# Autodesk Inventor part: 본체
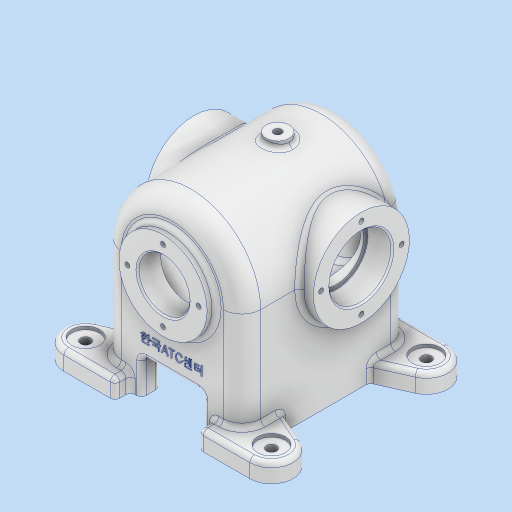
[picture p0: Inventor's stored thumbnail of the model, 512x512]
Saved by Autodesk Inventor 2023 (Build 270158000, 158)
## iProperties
Created: 2024-09
Part Number: 본체
Material: 알루미늄 6061
Document SubType Name: Modeling
Designer: asung
Density: 2.7 g/cm^3
Appearance: 알루미늄 - 평지
Mass: 1413.69 g
Surface Area: 1146.32 cm^2
Volume: 523.59 cm^3
Author: asung
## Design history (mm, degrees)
sketch "스케치1"
  geometry: L1 (-45, 0)-(45, 0); L2 (45, 0)-(45, -76); L3 (45, -76)-(-45, -76); L4 (-45, -76)-(-45, 0); L5 (-45, 0)-(45, -76); L6 (45, 0)-(-45, -76); L7 (-20, -53)-(20, -53); L8 (20, -53)-(20, -76); L9 (20, -76)-(-20, -76); L10 (-20, -76)-(-20, -53); L11 (-20, -53)-(20, -76); L12 (20, -53)-(-20, -76); C1 r 45 at (0, 0); 9 further points
  constraints: 24 end point, 7 midpoint, 4 parallel, 2 coincident, 2 horizontal, 2 perpendicular, 1 centre point
  dimensions: "d0" = 90 diameter of C1; "d2" = 90 distance of L2.end L3.end; "d3" = 76 distance of L1.end L2.end; "d4" = 40 distance of L8.end L9.end; "d5" = 23 distance of L7.end L8.end
extrude "돌출1" new body sketch "스케치1" stored distance "d6" = 108; taper "d7" = 0 deg
sketch "스케치2"
  geometry: C1 r 28.5 at (0, 0); 1 further point
  constraints: 1 centre point, 1 coincident
  dimensions: "d8" = 57 diameter of C1
extrude "돌출2" join sketch "스케치2" distance "d9" = 6; taper "d10" = 0 deg
node "작업 평면2"
sketch "스케치3"
  geometry: L1 (28.5, 60)-(-28.5, 60) reference; C1 r 31 at (0, -14); 2 further points
  constraints: 1 centre point, 1 midpoint, 1 vertical alignment
  dimensions: "d80" = 62 diameter of C1; "d81" = 74 distance from line of L1 C1.centre
extrude "돌출3" join sketch "스케치3" stored distance "d13" = 6; taper "d14" = 0 deg
sketch "스케치6"
  geometry: L1 (-28.5, 54)-(-28.5, 60) reference; L2 (-28.5, 60)-(28.5, 60) reference; L3 (28.5, 60)-(28.5, 54) reference; L4 (28.5, 54)-(45, 54) reference; L5 (45, 54)-(45, -54) reference; L6 (45, -54)-(-53, -54) reference; L7 (-53, -54)-(-53, 54) reference; L8 (-53, 54)-(-28.5, 54) reference; L9 (0, -54)-(0, 54) reference; L10 (0, -54)-(0, 60); L11 (28.5, 60)-(-28.5, 60) reference; L12 (0, -45)-(33, -45); L13 (36, -42)-(36, 42); L14 (33, 45)-(0, 45); L15 (0, 45)-(0, -45); A1 r 3 centre (33, -42) between (33, -45) and (36, -42); A2 r 3 centre (33, 42) between (36, 42) and (33, 45); 5 further points
  constraints: 10 end point, 4 point on circle, 4 tangent, 2 centre point, 2 parallel, 1 equal radius, 1 horizontal, 1 midpoint, 1 perpendicular, 1 point on line
  dimensions: "d29" = 9 distance between parallel lines of L13 L5; "d30" = 9 distance between parallel lines of L12 L6; "d31" = 9 distance between parallel lines of L4 L14; "d32" = 3 radius of A1
revolve "회전1" sketch "스케치6" stored, may be unused: angle "d33" = 90 deg
sketch "스케치7"
  geometry: C1 r 28.5 at (0, 0) reference; 2 further points
  constraints: 1 coincident
hole "구멍3" sketch "스케치7" at (0, 0) diameter "d34" = 33; stored, may be unused: countersink angle "d38" = 90 deg, drill point angle "d40" = 118 deg; dims "d35" = 6, "d36" = 40, "d37" = 16, "d39" = 60
chamfer "모따기1" distance "d41" = 1; stored, may be unused: second distance "d42" = 2, angle "d43" = 45 deg
fillet "모깎기1" dims "d44" = 12
node "작업 평면3"
sketch "스케치11" dims "d69" = 46
  geometry: C1 r 16.5 at (0, 0) reference; 3 further points
  constraints: 2 vertical alignment, 1 coincident, 2 other
hole "구멍6" sketch "스케치11" at (0, 23) diameter "d70" = 3.242; stored, may be unused: countersink angle "d74" = 90 deg, drill point angle "d76" = 118 deg; dims "d71" = 8, "d72" = 4, "d73" = 2, "d75" = 10
sketch "스케치12"
  geometry: C1 r 31 at (0, 0) reference; 2 further points
  constraints: 1 coincident
hole "구멍7" sketch "스케치12" at (0, 0) diameter "d82" = 35; stored, may be unused: countersink angle "d86" = 90 deg, drill point angle "d88" = 118 deg; dims "d83" = 8, "d84" = 40, "d85" = 16, "d87" = 100
sketch "스케치13"
  geometry: C1 r 31 at (0, 0) reference; 2 further points
  constraints: 1 coincident
hole "구멍8" sketch "스케치13" at (0, 0) diameter "d89" = 35; stored, may be unused: countersink angle "d93" = 90 deg, drill point angle "d95" = 118 deg; dims "d90" = 6, "d91" = 40, "d92" = 16, "d94" = 100
chamfer "모따기2" distance "d96" = 1; stored, may be unused: second distance "d97" = 2, angle "d98" = 45 deg
fillet "모깎기4" dims "d99" = 0.3
fillet "모깎기5" dims "d100" = 3
node "작업 평면5"
sketch "스케치14"
  geometry: L1 (48.5, 114)-(-8.5, 114) reference; L2 (74, 9)-(74, 71) reference; C1 r 7.5 at (20, 40); 2 further points
  constraints: 1 centre point, 1 midpoint, 1 vertical alignment
  dimensions: "d102" = 15 diameter of C1; "d103" = 74 distance from line of L1 C1.centre
extrude "돌출5" join sketch "스케치14" stored distance "d104" = 10; taper "d105" = 0 deg
fillet "모깎기6" dims "d110" = 3
sketch "스케치16"
  geometry: C1 r 7.5 at (0, 0) reference; 2 further points
  constraints: 1 coincident
hole "구멍9" sketch "스케치16" at (0, 0) diameter "d111" = 5.1881; stored, may be unused: countersink angle "d115" = 90 deg, drill point angle "d117" = 118 deg; dims "d112" = 20, "d113" = 40, "d114" = 16, "d116" = 21
sketch "스케치18" dims "d125" = 52
  geometry: C1 r 31 at (0, 0) reference; C2 r 21 at (0, 0) reference; 3 further points
  constraints: 2 vertical alignment, 1 coincident, 2 other
hole "구멍11" sketch "스케치18" at (0, 26) diameter "d126" = 3.242; stored, may be unused: countersink angle "d130" = 90 deg, drill point angle "d132" = 118 deg; dims "d127" = 8, "d128" = 4, "d129" = 2, "d131" = 10
sketch "스케치19"
  geometry: L1 (0, 0)-(-13, 0) reference; L2 (0, 0)-(0, 108) reference; L3 (-13, 108)-(0, 108) reference; L4 (-25, 96)-(-25, 12) reference; L5 (65, 12)-(65, 96) reference; L6 (40, 108)-(53, 108) reference; L7 (40, 0)-(40, 108) reference; L8 (53, 0)-(40, 0) reference; L9 (-40, -10)-(-7, -10); L10 (-7, -10)-(-7, 0); L11 (-25, 26)-(-45.693, 16.79); L12 (-25, 54)-(65, 54); L13 (18.379, 114)-(21.621, 114) reference; L14 (40, 0)-(0, 0) reference; L15 (20, 0)-(20, 108); L16 (0, 108)-(40, 108) reference; L17 (20, 114)-(20, 108); L18 (21.621, 104)-(21.621, 114) reference; L19 (-7, 118)-(-7, 108); L20 (-40, 118)-(-7, 118); L21 (-25, 82)-(-45.693, 91.21); L22 (47, -10)-(47, 0); L23 (80, -10)-(47, -10); L24 (65, 26)-(85.693, 16.79); L25 (65, 82)-(85.693, 91.21); L26 (80, 118)-(47, 118); L27 (47, 118)-(47, 108); A1 r 12 centre (-13, 12) between (-25, 12) and (-13, 0) reference; A2 r 12 centre (-13, 96) between (-13, 108) and (-25, 96) reference; A3 r 12 centre (53, 12) between (53, 0) and (65, 12) reference; A4 r 12 centre (53, 96) between (65, 96) and (53, 108) reference; A5 r 14 centre (-40, 4) between (-40, -10) and (-45.693, 16.79); A6 r 14 centre (-40, 104) between (-40, 118) and (-45.693, 91.21); A7 r 14 centre (80, 4) between (80, -10) and (85.693, 16.79); A8 r 14 centre (80, 104) between (80, 118) and (85.693, 91.21); 7 further points
  constraints: 30 end point, 18 symmetric about line, 8 point on circle, 5 midpoint, 4 centre point, 2 point on line, 2 tangent, 1 horizontal, 1 parallel, 1 perpendicular, 3 other
  dimensions: "d136" = 28 diameter of A5; "d137" = 60 horizontal distance of point (20, 54) A5.centre; "d138" = 18 distance between parallel lines of L10 L4; "d139" = 36 vertical distance of L9.start L11.start; "d140" = 50 vertical distance of L12.start A5.centre; "d199" = 36 vertical distance of L20.start L21.start (derived); "d200" = 36 vertical distance of L24.start L23.start (derived); "d201" = 36 vertical distance of L26.start L25.start (derived)
extrude "돌출7" join sketch "스케치19" distance "d141" = 12; taper "d142" = 0 deg
fillet "모깎기7" dims "d143" = 3
sketch "스케치21"
  geometry: L1 (-7, -7)-(-7, -3) reference; L2 (0, 0)-(-4, 0) reference; L3 (0, 0)-(0, 108) reference; L4 (-4, 108)-(0, 108) reference; L5 (-7, 111)-(-7, 115) reference; L6 (-10, 118)-(-40, 118) reference; L7 (-45.693, 91.21)-(-25, 82) reference; L8 (-25, 82)-(-25, 27.949) reference; L9 (-26.78, 25.208)-(-45.693, 16.79) reference; L10 (-40, -10)-(-10, -10) reference; L11 (56, 96)-(56, 12) reference; L12 (50, -10)-(80, -10) reference; L13 (85.693, 16.79)-(66.78, 25.208) reference; L14 (65, 27.949)-(65, 80.051) reference; L15 (66.78, 82.792)-(85.693, 91.21) reference; L16 (80, 118)-(50, 118) reference; L17 (47, 115)-(47, 111) reference; L18 (40, 108)-(44, 108) reference; L19 (40, 0)-(40, 108) reference; L20 (44, 0)-(40, 0) reference; L21 (47, -3)-(47, -7) reference; L22 (53, 9)-(-13, 9); L23 (-16, 12)-(-16, 96); L24 (-13, 99)-(53, 99); L25 (56, 96)-(56, 12); L26 (56, 9)-(-16, 99); L27 (-16, 9)-(56, 99); A1 r 3 centre (-10, -7) between (-10, -10) and (-7, -7) reference; A2 r 3 centre (-4, -3) between (-4, 0) and (-7, -3) reference; A3 r 3 centre (-4, 111) between (-7, 111) and (-4, 108) reference; A4 r 3 centre (-10, 115) between (-7, 115) and (-10, 118) reference; A5 r 14 centre (-40, 104) between (-40, 118) and (-45.693, 91.21) reference; A6 r 3 centre (-28, 27.949) between (-26.78, 25.208) and (-25, 27.949) reference; A7 r 14 centre (-40, 4) between (-45.693, 16.79) and (-40, -10) reference; A8 r 3 centre (50, -7) between (47, -7) and (50, -10) reference; A9 r 14 centre (80, 4) between (80, -10) and (85.693, 16.79) reference; A10 r 3 centre (68, 27.949) between (65, 27.949) and (66.78, 25.208) reference; A11 r 3 centre (68, 80.051) between (66.78, 82.792) and (65, 80.051) reference; A12 r 14 centre (80, 104) between (85.693, 91.21) and (80, 118) reference; A13 r 3 centre (50, 115) between (50, 118) and (47, 115) reference; A14 r 3 centre (44, 111) between (44, 108) and (47, 111) reference; A15 r 3 centre (44, -3) between (47, -3) and (44, 0) reference; A16 r 3 centre (-13, 12) between (-16, 12) and (-13, 9); A17 r 3 centre (-13, 96) between (-13, 99) and (-16, 96); A18 r 3 centre (53, 12) between (53, 9) and (56, 12); A19 r 3 centre (53, 96) between (56, 96) and (53, 99); 4 further points
  constraints: 12 end point, 8 point on circle, 8 point on line, 8 tangent, 4 centre point, 3 equal radius, 2 midpoint, 2 parallel, 1 horizontal, 1 perpendicular
  dimensions: "d149" = 9 distance between parallel lines of L8 L23; "d150" = 9 distance between parallel lines of L14 L25; "d151" = 9 distance between parallel lines of L4 L24; "d152" = 9 distance between parallel lines of L22 L2; "d153" = 3 radius of A16 (derived)
  node "투영된 루프4"
  node "투영된 루프5"
sketch "스케치22"
  geometry: L1 (38.3, -14.283)-(53, -14.283) reference; L2 (54, -15.652)-(54, -27.659) reference; L3 (54, -27.659)-(48, -27.659) reference; L4 (45, -30.984)-(45, -76) reference; L5 (45, -76)-(20, -76) reference; L6 (-20, -76)-(-45, -76) reference; L7 (-45, -76)-(-45, -30.984) reference; L8 (-48, -27.659)-(-54, -27.659) reference; L9 (-54, -27.659)-(-54, -15.652) reference; L10 (-53, -14.283)-(-38.3, -14.283) reference; L11 (-38, -13.86)-(-38, -10.5) reference; L12 (-38, -10.5)-(-34.435, -10.5) reference; L13 (34.435, -10.5)-(38, -10.5) reference; L14 (38, -10.5)-(38, -13.86) reference; L15 (38, 13.86)-(38, 10.5) reference; L16 (38, 10.5)-(34.435, 10.5) reference; L17 (-34.435, 10.5)-(-38, 10.5) reference; L18 (-38, 10.5)-(-38, 13.86) reference; L19 (-38.3, 14.283)-(-53, 14.283) reference; L20 (-54, 15.652)-(-54, 27.659) reference; L21 (-54, 27.659)-(-37.199, 27.659) reference; L22 (37.199, 27.659)-(54, 27.659) reference; L23 (54, 27.659)-(54, 15.652) reference; L24 (53, 14.283)-(38.3, 14.283) reference; L25 (-36, -45)-(-36, -27); L26 (20, -76)-(20, -53) reference; L27 (20, -53)-(-20, -53) reference; L28 (-20, -53)-(-20, -76) reference; L29 (-36, -45)-(-36, -76); L30 (-60, -76)-(-30, -76) reference; L31 (30, -76)-(60, -76) reference; L32 (36, -76)-(36, -27); L33 (36, -76)-(89.801, -76); A1 r 36 centre (0, 0) between (-34.435, -10.5) and (34.435, -10.5) reference; A2 r 36 centre (0, 0) between (34.435, 10.5) and (-34.435, 10.5) reference; A3 r 45 centre (0, 0) between (34.369, 29.047) and (-34.369, 29.047) reference; A4 r 45 centre (0, 0) between (-36, -27) and (36, -27); 5 further points
  constraints: 8 end point, 2 point on circle, 2 point on line, 1 centre point, 1 coincident, 1 horizontal, 1 perpendicular, 1 vertical, 12 other
  dimensions: "d156" = 90 diameter of A4; "d162" = 9 distance between parallel lines of L4 L32
extrude "돌출11" cut sketch "스케치22" stored distance "d163" = 84; taper "d164" = 0 deg
node "작업 평면6"
node "작업 평면7"
node "작업 평면8"
sketch "스케치24"
  geometry: L1 (28.5, 60)-(-28.5, 60) reference; C1 r 7.5 at (0, -14); 2 further points
  constraints: 1 centre point, 1 midpoint, 1 vertical alignment
  dimensions: "d169" = 15 diameter of C1; "d170" = 74 distance from line of L1 C1.centre
extrude "돌출12" join sketch "스케치24" stored distance "d171" = 10; taper "d172" = 0 deg
fillet "모깎기9" dims "d173" = 3
sketch "스케치25"
  geometry: C1 r 7.5 at (0, 0) reference; 2 further points
  constraints: 1 coincident
hole "구멍12" sketch "스케치25" at (0, 0) diameter "d174" = 5.1881; stored, may be unused: countersink angle "d178" = 90 deg, drill point angle "d180" = 118 deg; dims "d175" = 20, "d176" = 4, "d177" = 2, "d179" = 21
fillet "모깎기10" dims "d181" = 3
fillet "모깎기11" dims "d182" = 3
fillet "모깎기14" dims "d185" = 3
fillet "모깎기15" dims "d186" = 3
fillet "모깎기16" dims "d187" = 3
sketch "스케치26"
  geometry: A1 r 11 centre (80, -104) between (80, -115) and (84.473, -93.95) reference; A2 r 11 centre (80, -4) between (84.473, -14.05) and (80, 7) reference; A3 r 11 centre (-40, -104) between (-44.473, -93.95) and (-40, -115) reference; A4 r 14 centre (-40, -4) between (-40, 10) and (-45.693, -16.79) reference; 5 further points
  constraints: 4 coincident
hole "구멍13" sketch "스케치26" at (80, -104), (80, -4), (-40, -104), (-40, -4) diameter "d188" = 6.6; stored, may be unused: countersink angle "d192" = 90 deg, drill point angle "d194" = 118 deg; dims "d189" = 20, "d190" = 18, "d191" = 2, "d193" = 21
fillet "모깎기17" dims "d195" = 3
sketch "스케치27"
  geometry: L1 (60, -76)-(74, -76) reference; L2 (-17, -53)-(17, -53) reference; 4 further points
  constraints: 1 midpoint, 1 vertical alignment, 1 other
  dimensions: "d196" = 35 distance from line of L1 point (0, -41)
feature "엠보싱1" sketch "스케치27" dims "d197" = 0.5, "d198" = 0
node "솔리드1"
pattern_circular "원형 패턴2" dims angle "d78" = 360 deg
mirror "미러3"
pattern_circular "원형 패턴3" dims angle "d134" = 360 deg
mirror "미러4"
node "투영된 루프1"
node "투영된 루프2"
node "투영된 루프3"
node "절단 모서리 투영1"
node "절단 모서리 투영3"
feature "A9D066F2-1C7D-4E18-AEED-F7BC21143FA4" dims "d34" = 33, "d35" = 6, "d36" = 40, "d37" = 16, "d38" = 90 deg, "d39" = 60, "d40" = 118 deg
other parameters: "d11" = 54, "d57" = -125, "d101" = -125, "d165" = 4, "d168" = -4
